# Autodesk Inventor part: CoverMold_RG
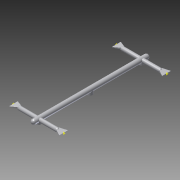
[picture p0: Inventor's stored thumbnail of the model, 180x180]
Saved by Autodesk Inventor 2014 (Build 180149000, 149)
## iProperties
Created: 2009-12
Part Number: CoverMold_RG
Document SubType Name: Modeling
Designer: gaom
Density: 1 g/cm^3
Material: Generic
Appearance: Default
Author: gaom
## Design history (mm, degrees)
node "Gate Location 1_PZ:1"
node "Gate Location 1_PZ:2"
node "Gate Location 1_PZ:3"
node "Gate Location 1_PZ:4"
workplane "Work Plane1"
sketch "Sketch1"
  geometry: L1 (-40, -110)-(0, -110); L2 (0, -110)-(40, -110); L3 (0, -110)-(0, 0) reference; L4 (0, 0)-(0, 110); L5 (0, 110)-(-40, 110); L6 (0, 110)-(40, 110)
  constraints: 12 end point, 8 equal length, 1 perpendicular, 1 vertical, 1 other
  dimensions: "d1" = 110 distance of L1.end L3.end; "d2" = 40 distance of L1.start L1.end
node "Runner Segment1"
  sketch "Sketch2"
    geometry: C1 r 5 at (0, 0); 1 further point
    constraints: 1 centre point, 1 coincident
    dimensions: "d3" = 10 diameter of C1
  sketch "Sketch3"
    geometry: L1 (0, 5)-(0, -5); A1 r 5 centre (0, 0) between (0, -5) and (0, 5); 1 further point
    constraints: 2 end point, 2 point on circle, 1 centre point, 1 coincident, 1 midpoint, 1 vertical
    dimensions: "d6" = 10 diameter of A1
  sketch "Sketch4"
    geometry: C1 r 5 at (0, 0); 1 further point
    constraints: 1 centre point, 1 coincident
    dimensions: "d8" = 10 diameter of C1
node "Runner Segment2"
  sketch "Sketch5"
    geometry: C1 r 5 at (0, 0); 1 further point
    constraints: 1 centre point, 1 coincident
    dimensions: "d11" = 10 diameter of C1
  sketch "Sketch6"
    geometry: L1 (0, 5)-(0, -5); A1 r 5 centre (0, 0) between (0, 5) and (0, -5); 1 further point
    constraints: 2 end point, 2 point on circle, 1 centre point, 1 coincident, 1 midpoint, 1 vertical
    dimensions: "d14" = 10 diameter of A1
  sketch "Sketch7"
    geometry: C1 r 5 at (0, 0); 1 further point
    constraints: 1 centre point, 1 coincident
    dimensions: "d16" = 10 diameter of C1
node "Runner Segment3"
  sketch "Sketch8"
    geometry: C1 r 4 at (0, 0); 1 further point
    constraints: 1 centre point, 1 coincident
    dimensions: "d19" = 8 diameter of C1
  sketch "Sketch9"
    geometry: L1 (0, 4)-(0, -4); A1 r 4 centre (0, 0) between (0, 4) and (0, -4); 1 further point
    constraints: 2 end point, 2 point on circle, 1 centre point, 1 coincident, 1 midpoint, 1 vertical
    dimensions: "d22" = 8 diameter of A1
node "Runner Segment4"
  sketch "Sketch10"
    geometry: C1 r 4 at (0, 0); 1 further point
    constraints: 1 centre point, 1 coincident
    dimensions: "d24" = 8 diameter of C1
  sketch "Sketch11"
    geometry: L1 (0, 4)-(0, -4); A1 r 4 centre (0, 0) between (0, -4) and (0, 4); 1 further point
    constraints: 2 end point, 2 point on circle, 1 centre point, 1 coincident, 1 midpoint, 1 vertical
    dimensions: "d27" = 8 diameter of A1
node "Runner Segment5"
  sketch "Sketch12"
    geometry: C1 r 4 at (0, 0); 1 further point
    constraints: 1 centre point, 1 coincident
    dimensions: "d29" = 8 diameter of C1
  sketch "Sketch13"
    geometry: L1 (0, 4)-(0, -4); A1 r 4 centre (0, 0) between (0, -4) and (0, 4); 1 further point
    constraints: 2 end point, 2 point on circle, 1 centre point, 1 coincident, 1 midpoint, 1 vertical
    dimensions: "d32" = 8 diameter of A1
node "Runner Segment6"
  sketch "Sketch14"
    geometry: C1 r 4 at (0, 0); 1 further point
    constraints: 1 centre point, 1 coincident
    dimensions: "d34" = 8 diameter of C1
  sketch "Sketch15"
    geometry: L1 (0, 4)-(0, -4); A1 r 4 centre (0, 0) between (0, -4) and (0, 4); 1 further point
    constraints: 2 end point, 2 point on circle, 1 centre point, 1 coincident, 1 midpoint, 1 vertical
    dimensions: "d37" = 8 diameter of A1
node "Client Feature1"
  sketch "3D Sketch1"
  workplane "Work Plane2"
node "Client Feature2"
  sketch "3D Sketch2"
  workplane "Work Plane3"
node "Client Feature3"
  sketch "3D Sketch3"
  workplane "Work Plane4"
node "Client Feature4"
  sketch "3D Sketch4"
  workplane "Work Plane5"
sketch "Sketch24"
  geometry: C1 r 5 at (0, 0)
  constraints: 1 centre point
extrude "Extrusion3" join sketch "Sketch24" distance "d95" = 8; taper "d96" = 5 deg
sketch "Sketch25"
  geometry: C1 r 4 at (0, 0)
  constraints: 1 centre point
extrude "Extrusion4" join sketch "Sketch25" distance "d97" = 8; taper "d98" = 5 deg
sketch "Sketch26"
  geometry: C1 r 4 at (0, 0)
  constraints: 1 centre point
extrude "Extrusion5" join sketch "Sketch26" distance "d99" = 8; taper "d100" = 5 deg
body "Solid1"
sweep "Sweep1" dims "d4" = 0
revolve "Revolution1" stored, may be unused: angle "d7" = 180 deg
extrude "Extrusion1" join sketch "Sketch4" distance "d9" = 10; taper "d10" = 0 deg
sweep "Sweep2" dims "d12" = 0
revolve "Revolution2" stored, may be unused: angle "d15" = 180 deg
extrude "Extrusion2" join sketch "Sketch7" distance "d17" = 10; taper "d18" = 0 deg
sweep "Sweep3" dims "d20" = 0
revolve "Revolution3" stored, may be unused: angle "d23" = 180 deg
sweep "Sweep4" dims "d25" = 0
revolve "Revolution4" stored, may be unused: angle "d28" = 180 deg
sweep "Sweep5" dims "d30" = 0
revolve "Revolution5" stored, may be unused: angle "d33" = 180 deg
sweep "Sweep6" dims "d35" = 0
revolve "Revolution6" stored, may be unused: angle "d38" = 180 deg
sketch "Sketch16"
  geometry: L1 (-9, 0)-(9, 0); L2 (-8.937, 1.2)-(8.937, 1.2); L3 (-9, 0)-(-8.937, 1.2); L4 (9, 0)-(8.937, 1.2); 1 further point
  constraints: 8 end point, 1 horizontal, 1 midpoint
  dimensions: "d40" = 18 distance of L1.start L1.end; "d41" = 1.2 distance between parallel lines of L1 L2; "d42" = 87 deg angle of L1 L3; "d43" = 87 deg angle of L1 L4 (= d42)
sketch "Sketch17"
  geometry: L1 (-3, 0)-(3, 0); L2 (-2.843, 3)-(2.843, 3); L3 (-3, 0)-(-2.843, 3); L4 (3, 0)-(2.843, 3); 1 further point
  constraints: 8 end point, 1 horizontal, 1 midpoint
  dimensions: "d44" = 6 distance of L1.start L1.end; "d45" = 3 distance between parallel lines of L1 L2; "d46" = 87 deg angle of L1 L3; "d47" = 87 deg angle of L1 L4 (= d46)
loft "Loft1" dims "d48" = 0, "d49" = 90 deg, "d50" = 0, "d51" = 90 deg
thicken "Thicken1" dims "d52" = 1
sketch "Sketch18"
  geometry: L1 (-9, 0)-(9, 0); L2 (-8.937, 1.2)-(8.937, 1.2); L3 (-9, 0)-(-8.937, 1.2); L4 (9, 0)-(8.937, 1.2); 1 further point
  constraints: 8 end point, 1 horizontal, 1 midpoint
  dimensions: "d54" = 18 distance of L1.start L1.end; "d55" = 1.2 distance between parallel lines of L1 L2; "d56" = 87 deg angle of L1 L3; "d57" = 87 deg angle of L1 L4 (= d56)
sketch "Sketch19"
  geometry: L1 (-3, 0)-(3, 0); L2 (-2.843, 3)-(2.843, 3); L3 (-3, 0)-(-2.843, 3); L4 (3, 0)-(2.843, 3); 1 further point
  constraints: 8 end point, 1 horizontal, 1 midpoint
  dimensions: "d58" = 6 distance of L1.start L1.end; "d59" = 3 distance between parallel lines of L1 L2; "d60" = 87 deg angle of L1 L3; "d61" = 87 deg angle of L1 L4 (= d60)
loft "Loft2" dims "d62" = 0, "d63" = 90 deg, "d64" = 0, "d65" = 90 deg
thicken "Thicken2" dims "d66" = 1
sketch "Sketch20"
  geometry: L1 (-9, 0)-(9, 0); L2 (-8.937, 1.2)-(8.937, 1.2); L3 (-9, 0)-(-8.937, 1.2); L4 (9, 0)-(8.937, 1.2); 1 further point
  constraints: 8 end point, 1 horizontal, 1 midpoint
  dimensions: "d68" = 18 distance of L1.start L1.end; "d69" = 1.2 distance between parallel lines of L1 L2; "d70" = 87 deg angle of L1 L3; "d71" = 87 deg angle of L1 L4 (= d70)
sketch "Sketch21"
  geometry: L1 (-3, 0)-(3, 0); L2 (-2.843, 3)-(2.843, 3); L3 (-3, 0)-(-2.843, 3); L4 (3, 0)-(2.843, 3); 1 further point
  constraints: 8 end point, 1 horizontal, 1 midpoint
  dimensions: "d72" = 6 distance of L1.start L1.end; "d73" = 3 distance between parallel lines of L1 L2; "d74" = 87 deg angle of L1 L3; "d75" = 87 deg angle of L1 L4 (= d74)
loft "Loft3" dims "d76" = 0, "d77" = 90 deg, "d78" = 0, "d79" = 90 deg
thicken "Thicken3" dims "d80" = 1
sketch "Sketch22"
  geometry: L1 (-9, 0)-(9, 0); L2 (-8.937, 1.2)-(8.937, 1.2); L3 (-9, 0)-(-8.937, 1.2); L4 (9, 0)-(8.937, 1.2); 1 further point
  constraints: 8 end point, 1 horizontal, 1 midpoint
  dimensions: "d82" = 18 distance of L1.start L1.end; "d83" = 1.2 distance between parallel lines of L1 L2; "d84" = 87 deg angle of L1 L3; "d85" = 87 deg angle of L1 L4 (= d84)
sketch "Sketch23"
  geometry: L1 (-3, 0)-(3, 0); L2 (-2.843, 3)-(2.843, 3); L3 (-3, 0)-(-2.843, 3); L4 (3, 0)-(2.843, 3); 1 further point
  constraints: 8 end point, 1 horizontal, 1 midpoint
  dimensions: "d86" = 6 distance of L1.start L1.end; "d87" = 3 distance between parallel lines of L1 L2; "d88" = 87 deg angle of L1 L3; "d89" = 87 deg angle of L1 L4 (= d88)
loft "Loft4" dims "d90" = 0, "d91" = 90 deg, "d92" = 0, "d93" = 90 deg
thicken "Thicken4" dims "d94" = 1
other parameters: "d0" = 0, "d21" = 0, "d26" = 0, "d31" = 0, "d36" = 0, "d117" = 1, "d118" = 1, "d119" = 1, "d120" = 1
